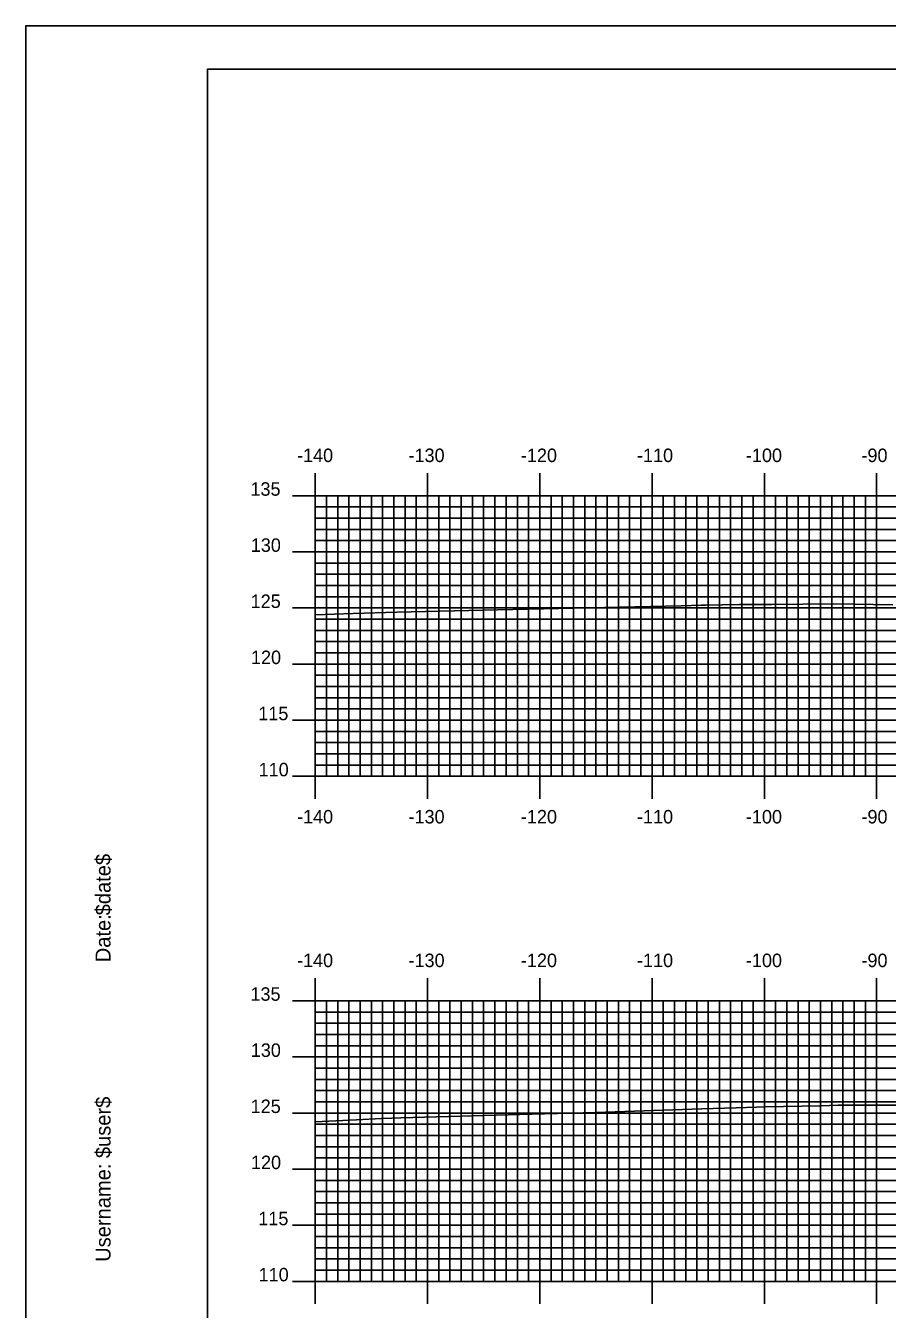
# Model space of a CAD drawing. Extents: x 842569 to 842912, y 363538 to 363758.
# Drawn here: x 842568.6 to 842645.4, y 363643.2 to 363757.6 of the extents above; entities that cross this region are included whole.
import ezdxf

# ---------------------------------------------------------------- set-up
doc = ezdxf.new("R2010")
doc.units = 0
for name, color, linetype in [('BORDER', 7, 'Continuous'), ('H_V ANNOTATION', 7, 'Continuous'), ('M_Roadway_Centerline', 7, 'Continuous'), ('MAJOR', 7, 'Continuous'), ('MINOR', 7, 'Continuous'), ('PLOT BOUNDARY', 7, 'Continuous'), ('S_Roadway_Centerline', 7, 'Continuous')]:
    doc.layers.add(name, color=color, linetype=linetype)

msp = doc.modelspace()

# ---------------------------------------------------------------- linework, layer by layer
at = {"layer": 'BORDER'}
msp.add_lwpolyline([(842584.8, 363543.72), (842904.8, 363543.72), (842904.8, 363753.72), (842584.8, 363753.72)], close=True, dxfattribs=at)
at = {"layer": 'MAJOR'}
for p, q in [((842594.4, 363717.73), (842594.4, 363715.72)), ((842604.4, 363717.73), (842604.4, 363715.72)), ((842614.4, 363717.73), (842614.4, 363715.72)), ((842624.4, 363717.73), (842624.4, 363715.72)), ((842634.4, 363717.73), (842634.4, 363715.72)), ((842644.4, 363717.73), (842644.4, 363715.72)), ((842592.39, 363715.72), (842594.4, 363715.72)), ((842594.4, 363715.72), (842874.4, 363715.72)), ((842594.4, 363690.72), (842594.4, 363715.72)), ((842594.4, 363690.72), (842594.4, 363715.72)), ((842594.4, 363715.72), (842874.4, 363715.72)), ((842604.4, 363690.72), (842604.4, 363715.72)), ((842614.4, 363690.72), (842614.4, 363715.72)), ((842624.4, 363690.72), (842624.4, 363715.72)), ((842634.4, 363690.72), (842634.4, 363715.72)), ((842644.4, 363690.72), (842644.4, 363715.72)), ((842592.39, 363710.72), (842594.4, 363710.72)), ((842594.4, 363710.72), (842874.4, 363710.72)), ((842592.39, 363705.72), (842594.4, 363705.72)), ((842594.4, 363705.72), (842874.4, 363705.72)), ((842592.39, 363700.72), (842594.4, 363700.72)), ((842594.4, 363700.72), (842874.4, 363700.72)), ((842592.39, 363695.72), (842594.4, 363695.72)), ((842594.4, 363695.72), (842874.4, 363695.72)), ((842592.39, 363690.72), (842594.4, 363690.72)), ((842594.4, 363690.72), (842874.4, 363690.72)), ((842594.4, 363690.72), (842874.4, 363690.72)), ((842594.4, 363688.72), (842594.4, 363690.72)), ((842604.4, 363688.72), (842604.4, 363690.72)), ((842614.4, 363688.72), (842614.4, 363690.72)), ((842624.4, 363688.72), (842624.4, 363690.72)), ((842634.4, 363688.72), (842634.4, 363690.72)), ((842644.4, 363688.72), (842644.4, 363690.72)), ((842594.4, 363672.73), (842594.4, 363670.72)), ((842604.4, 363672.73), (842604.4, 363670.72)), ((842614.4, 363672.73), (842614.4, 363670.72)), ((842624.4, 363672.73), (842624.4, 363670.72)), ((842634.4, 363672.73), (842634.4, 363670.72)), ((842644.4, 363672.73), (842644.4, 363670.72)), ((842592.39, 363670.72), (842594.4, 363670.72)), ((842594.4, 363670.72), (842874.4, 363670.72)), ((842594.4, 363645.72), (842594.4, 363670.72)), ((842594.4, 363645.72), (842594.4, 363670.72)), ((842594.4, 363670.72), (842874.4, 363670.72)), ((842604.4, 363645.72), (842604.4, 363670.72)), ((842614.4, 363645.72), (842614.4, 363670.72)), ((842624.4, 363645.72), (842624.4, 363670.72)), ((842634.4, 363645.72), (842634.4, 363670.72)), ((842644.4, 363645.72), (842644.4, 363670.72)), ((842592.39, 363665.72), (842594.4, 363665.72)), ((842594.4, 363665.72), (842874.4, 363665.72)), ((842592.39, 363660.72), (842594.4, 363660.72)), ((842594.4, 363660.72), (842874.4, 363660.72)), ((842592.39, 363655.72), (842594.4, 363655.72)), ((842594.4, 363655.72), (842874.4, 363655.72)), ((842592.39, 363650.72), (842594.4, 363650.72)), ((842594.4, 363650.72), (842874.4, 363650.72)), ((842592.39, 363645.72), (842594.4, 363645.72)), ((842594.4, 363645.72), (842874.4, 363645.72)), ((842594.4, 363645.72), (842874.4, 363645.72)), ((842594.4, 363643.72), (842594.4, 363645.72)), ((842604.4, 363643.72), (842604.4, 363645.72)), ((842614.4, 363643.72), (842614.4, 363645.72)), ((842624.4, 363643.72), (842624.4, 363645.72)), ((842634.4, 363643.72), (842634.4, 363645.72)), ((842644.4, 363643.72), (842644.4, 363645.72))]:
    msp.add_line(p, q, dxfattribs=at)
at = {"layer": 'MINOR'}
for p, q in [((842595.4, 363690.72), (842595.4, 363715.72)), ((842596.4, 363690.72), (842596.4, 363715.72)), ((842597.4, 363690.72), (842597.4, 363715.72)), ((842598.4, 363690.72), (842598.4, 363715.72)), ((842599.4, 363690.72), (842599.4, 363715.72)), ((842600.4, 363690.72), (842600.4, 363715.72)), ((842601.4, 363690.72), (842601.4, 363715.72)), ((842602.4, 363690.72), (842602.4, 363715.72)), ((842603.4, 363690.72), (842603.4, 363715.72)), ((842605.4, 363690.72), (842605.4, 363715.72)), ((842606.4, 363690.72), (842606.4, 363715.72)), ((842607.4, 363690.72), (842607.4, 363715.72)), ((842608.4, 363690.72), (842608.4, 363715.72)), ((842609.4, 363690.72), (842609.4, 363715.72)), ((842610.4, 363690.72), (842610.4, 363715.72)), ((842611.4, 363690.72), (842611.4, 363715.72)), ((842612.4, 363690.72), (842612.4, 363715.72)), ((842613.4, 363690.72), (842613.4, 363715.72)), ((842615.4, 363690.72), (842615.4, 363715.72)), ((842616.4, 363690.72), (842616.4, 363715.72)), ((842617.4, 363690.72), (842617.4, 363715.72)), ((842618.4, 363690.72), (842618.4, 363715.72)), ((842619.4, 363690.72), (842619.4, 363715.72)), ((842620.4, 363690.72), (842620.4, 363715.72)), ((842621.4, 363690.72), (842621.4, 363715.72)), ((842622.4, 363690.72), (842622.4, 363715.72)), ((842623.4, 363690.72), (842623.4, 363715.72)), ((842625.4, 363690.72), (842625.4, 363715.72)), ((842626.4, 363690.72), (842626.4, 363715.72)), ((842627.4, 363690.72), (842627.4, 363715.72)), ((842628.4, 363690.72), (842628.4, 363715.72)), ((842629.4, 363690.72), (842629.4, 363715.72)), ((842630.4, 363690.72), (842630.4, 363715.72)), ((842631.4, 363690.72), (842631.4, 363715.72)), ((842632.4, 363690.72), (842632.4, 363715.72)), ((842633.4, 363690.72), (842633.4, 363715.72)), ((842635.4, 363690.72), (842635.4, 363715.72)), ((842636.4, 363690.72), (842636.4, 363715.72)), ((842637.4, 363690.72), (842637.4, 363715.72)), ((842638.4, 363690.72), (842638.4, 363715.72)), ((842639.4, 363690.72), (842639.4, 363715.72)), ((842640.4, 363690.72), (842640.4, 363715.72)), ((842641.4, 363690.72), (842641.4, 363715.72)), ((842642.4, 363690.72), (842642.4, 363715.72)), ((842643.4, 363690.72), (842643.4, 363715.72)), ((842594.4, 363714.72), (842874.4, 363714.72)), ((842594.4, 363714.72), (842596.4, 363714.72)), ((842594.4, 363713.72), (842874.4, 363713.72)), ((842594.4, 363713.72), (842596.4, 363713.72)), ((842594.4, 363712.72), (842874.4, 363712.72)), ((842594.4, 363712.72), (842596.4, 363712.72)), ((842594.4, 363711.72), (842874.4, 363711.72)), ((842594.4, 363711.72), (842596.4, 363711.72)), ((842594.4, 363709.72), (842874.4, 363709.72)), ((842594.4, 363709.72), (842596.4, 363709.72)), ((842594.4, 363708.72), (842874.4, 363708.72)), ((842594.4, 363708.72), (842596.4, 363708.72)), ((842594.4, 363707.72), (842874.4, 363707.72)), ((842594.4, 363707.72), (842596.4, 363707.72)), ((842594.4, 363706.72), (842874.4, 363706.72)), ((842594.4, 363706.72), (842596.4, 363706.72)), ((842594.4, 363704.72), (842874.4, 363704.72)), ((842594.4, 363704.72), (842596.4, 363704.72)), ((842594.4, 363703.72), (842874.4, 363703.72)), ((842594.4, 363703.72), (842596.4, 363703.72)), ((842594.4, 363702.72), (842874.4, 363702.72)), ((842594.4, 363702.72), (842596.4, 363702.72)), ((842594.4, 363701.72), (842874.4, 363701.72)), ((842594.4, 363701.72), (842596.4, 363701.72)), ((842594.4, 363699.72), (842874.4, 363699.72)), ((842594.4, 363699.72), (842596.4, 363699.72)), ((842594.4, 363698.72), (842874.4, 363698.72)), ((842594.4, 363698.72), (842596.4, 363698.72)), ((842594.4, 363697.72), (842874.4, 363697.72)), ((842594.4, 363697.72), (842596.4, 363697.72)), ((842594.4, 363696.72), (842874.4, 363696.72)), ((842594.4, 363696.72), (842596.4, 363696.72)), ((842594.4, 363694.72), (842874.4, 363694.72)), ((842594.4, 363694.72), (842596.4, 363694.72)), ((842594.4, 363693.72), (842874.4, 363693.72)), ((842594.4, 363693.72), (842596.4, 363693.72)), ((842594.4, 363692.72), (842874.4, 363692.72)), ((842594.4, 363692.72), (842596.4, 363692.72)), ((842594.4, 363691.72), (842874.4, 363691.72)), ((842594.4, 363691.72), (842596.4, 363691.72)), ((842595.4, 363645.72), (842595.4, 363670.72)), ((842596.4, 363645.72), (842596.4, 363670.72)), ((842597.4, 363645.72), (842597.4, 363670.72)), ((842598.4, 363645.72), (842598.4, 363670.72)), ((842599.4, 363645.72), (842599.4, 363670.72)), ((842600.4, 363645.72), (842600.4, 363670.72)), ((842601.4, 363645.72), (842601.4, 363670.72)), ((842602.4, 363645.72), (842602.4, 363670.72)), ((842603.4, 363645.72), (842603.4, 363670.72)), ((842605.4, 363645.72), (842605.4, 363670.72)), ((842606.4, 363645.72), (842606.4, 363670.72)), ((842607.4, 363645.72), (842607.4, 363670.72)), ((842608.4, 363645.72), (842608.4, 363670.72)), ((842609.4, 363645.72), (842609.4, 363670.72)), ((842610.4, 363645.72), (842610.4, 363670.72)), ((842611.4, 363645.72), (842611.4, 363670.72)), ((842612.4, 363645.72), (842612.4, 363670.72)), ((842613.4, 363645.72), (842613.4, 363670.72)), ((842615.4, 363645.72), (842615.4, 363670.72)), ((842616.4, 363645.72), (842616.4, 363670.72)), ((842617.4, 363645.72), (842617.4, 363670.72)), ((842618.4, 363645.72), (842618.4, 363670.72)), ((842619.4, 363645.72), (842619.4, 363670.72)), ((842620.4, 363645.72), (842620.4, 363670.72)), ((842621.4, 363645.72), (842621.4, 363670.72)), ((842622.4, 363645.72), (842622.4, 363670.72)), ((842623.4, 363645.72), (842623.4, 363670.72)), ((842625.4, 363645.72), (842625.4, 363670.72)), ((842626.4, 363645.72), (842626.4, 363670.72)), ((842627.4, 363645.72), (842627.4, 363670.72)), ((842628.4, 363645.72), (842628.4, 363670.72)), ((842629.4, 363645.72), (842629.4, 363670.72)), ((842630.4, 363645.72), (842630.4, 363670.72)), ((842631.4, 363645.72), (842631.4, 363670.72)), ((842632.4, 363645.72), (842632.4, 363670.72)), ((842633.4, 363645.72), (842633.4, 363670.72)), ((842635.4, 363645.72), (842635.4, 363670.72)), ((842636.4, 363645.72), (842636.4, 363670.72)), ((842637.4, 363645.72), (842637.4, 363670.72)), ((842638.4, 363645.72), (842638.4, 363670.72)), ((842639.4, 363645.72), (842639.4, 363670.72)), ((842640.4, 363645.72), (842640.4, 363670.72)), ((842641.4, 363645.72), (842641.4, 363670.72)), ((842642.4, 363645.72), (842642.4, 363670.72)), ((842643.4, 363645.72), (842643.4, 363670.72)), ((842594.4, 363669.72), (842874.4, 363669.72)), ((842594.4, 363669.72), (842596.4, 363669.72)), ((842594.4, 363668.72), (842874.4, 363668.72)), ((842594.4, 363668.72), (842596.4, 363668.72)), ((842594.4, 363667.72), (842874.4, 363667.72)), ((842594.4, 363667.72), (842596.4, 363667.72)), ((842594.4, 363666.72), (842874.4, 363666.72)), ((842594.4, 363666.72), (842596.4, 363666.72)), ((842594.4, 363664.72), (842874.4, 363664.72)), ((842594.4, 363664.72), (842596.4, 363664.72)), ((842594.4, 363663.72), (842874.4, 363663.72)), ((842594.4, 363663.72), (842596.4, 363663.72)), ((842594.4, 363662.72), (842874.4, 363662.72)), ((842594.4, 363662.72), (842596.4, 363662.72)), ((842594.4, 363661.72), (842874.4, 363661.72)), ((842594.4, 363661.72), (842596.4, 363661.72)), ((842594.4, 363659.72), (842874.4, 363659.72)), ((842594.4, 363659.72), (842596.4, 363659.72)), ((842594.4, 363658.72), (842874.4, 363658.72)), ((842594.4, 363658.72), (842596.4, 363658.72)), ((842594.4, 363657.72), (842874.4, 363657.72)), ((842594.4, 363657.72), (842596.4, 363657.72)), ((842594.4, 363656.72), (842874.4, 363656.72)), ((842594.4, 363656.72), (842596.4, 363656.72)), ((842594.4, 363654.72), (842874.4, 363654.72)), ((842594.4, 363654.72), (842596.4, 363654.72)), ((842594.4, 363653.72), (842874.4, 363653.72)), ((842594.4, 363653.72), (842596.4, 363653.72)), ((842594.4, 363652.72), (842874.4, 363652.72)), ((842594.4, 363652.72), (842596.4, 363652.72)), ((842594.4, 363651.72), (842874.4, 363651.72)), ((842594.4, 363651.72), (842596.4, 363651.72)), ((842594.4, 363649.72), (842874.4, 363649.72)), ((842594.4, 363649.72), (842596.4, 363649.72)), ((842594.4, 363648.72), (842874.4, 363648.72)), ((842594.4, 363648.72), (842596.4, 363648.72)), ((842594.4, 363647.72), (842874.4, 363647.72)), ((842594.4, 363647.72), (842596.4, 363647.72)), ((842594.4, 363646.72), (842874.4, 363646.72)), ((842594.4, 363646.72), (842596.4, 363646.72))]:
    msp.add_line(p, q, dxfattribs=at)
at = {"layer": 'PLOT BOUNDARY'}
msp.add_lwpolyline([(842568.61, 363537.6), (842908.61, 363537.6), (842908.61, 363757.6), (842568.61, 363757.6)], close=True, dxfattribs=at)
at = {"layer": 'S_Roadway_Centerline'}
for points in [[(842594.4, 363705.1), (842597.79, 363705.22), (842601.68, 363705.34), (842610.63, 363705.56), (842626.98, 363705.92), (842628.81, 363705.96), (842629.16, 363705.96), (842632.19, 363706.02), (842632.46, 363706.03), (842635.06, 363706.03), (842640.59, 363706.09), (842645.84, 363706)], [(842594.4, 363659.94), (842598.09, 363660.12), (842600.31, 363660.23), (842600.42, 363660.24), (842602.03, 363660.28), (842613.68, 363660.61), (842619.39, 363660.78), (842628.83, 363661.08), (842631.89, 363661.17), (842633.7, 363661.25), (842634.44, 363661.26), (842639.43, 363661.37), (842640.96, 363661.41), (842648.24, 363661.41)]]:
    msp.add_lwpolyline(points, dxfattribs=at)

# ---------------------------------------------------------------- texts
at = {"layer": 'BORDER'}
for s, p in [('$date$', (842576.17, 363678.33)), ('Date:', (842576.17, 363674.15)), ('$user$', (842576.17, 363656.7)), ('Username:', (842576.17, 363647.46))]:
    msp.add_text(s, height=1.339, rotation=90, dxfattribs=at).set_placement(p)
at = {"layer": 'H_V ANNOTATION'}
for s, p in [('-140', (842592.78, 363718.72)), ('-130', (842602.71, 363718.72)), ('-120', (842612.72, 363718.72)), ('-110', (842623.06, 363718.72)), ('-100', (842632.76, 363718.72)), ('-90', (842643.05, 363718.72)), ('135', (842588.63, 363715.72)), ('130', (842588.66, 363710.72)), ('125', (842588.65, 363705.72)), ('120', (842588.68, 363700.72)), ('115', (842589.33, 363695.72)), ('110', (842589.36, 363690.72)), ('-140', (842592.78, 363686.52)), ('-130', (842602.71, 363686.52)), ('-120', (842612.72, 363686.52)), ('-110', (842623.06, 363686.52)), ('-100', (842632.76, 363686.52)), ('-90', (842643.05, 363686.52)), ('-140', (842592.78, 363673.72)), ('-130', (842602.71, 363673.72)), ('-120', (842612.72, 363673.72)), ('-110', (842623.06, 363673.72)), ('-100', (842632.76, 363673.72)), ('-90', (842643.05, 363673.72)), ('135', (842588.63, 363670.72)), ('130', (842588.66, 363665.72)), ('125', (842588.65, 363660.72)), ('120', (842588.68, 363655.72)), ('115', (842589.33, 363650.72)), ('110', (842589.36, 363645.72))]:
    msp.add_text(s, height=1.2, dxfattribs=at).set_placement(p)
at = {"layer": 'M_Roadway_Centerline'}
for s, p in [('C', (842597.78, 363705.22)), ('L', (842597.79, 363705.22)), ('C', (842632.19, 363706.02)), ('L', (842632.19, 363706.01)), ('C', (842633.69, 363661.25)), ('L', (842633.7, 363661.25)), ('C', (842600.41, 363660.24)), ('L', (842600.42, 363660.23))]:
    msp.add_text(s, height=0.0146, dxfattribs=at).set_placement(p)
at = {"layer": 'MAJOR'}
for p in [(842594.39, 363690.72), (842594.39, 363645.72)]:
    msp.add_text('-', height=0.012, dxfattribs=at).set_placement(p)

doc.saveas('drawing.dxf')
